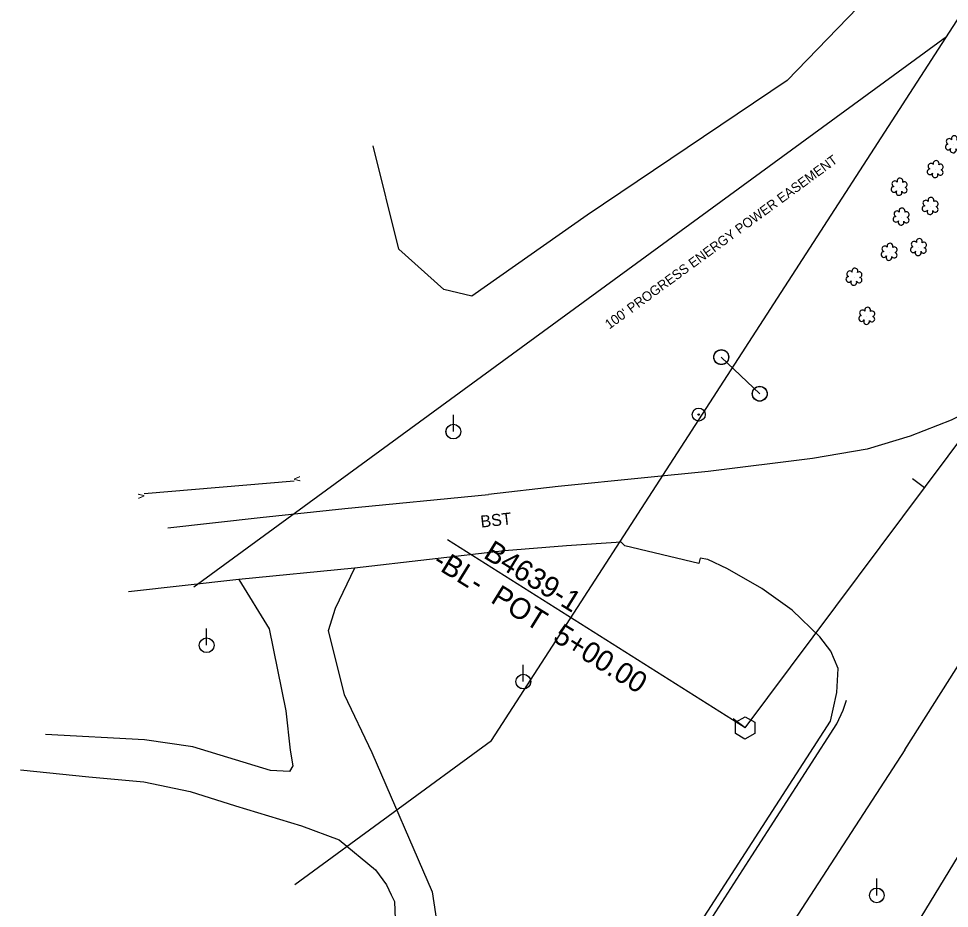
# Model space of a CAD drawing. Extents: x 1840200 to 1849051, y 348278 to 353012.
# Drawn here: x 1843953.5 to 1844264.2, y 349980.4 to 350277.2 of the extents above; entities that cross this region are included whole.
import ezdxf

# ---------------------------------------------------------------- set-up
doc = ezdxf.new("R2010")
doc.units = 0
for name, color, linetype in [('CTL GPS Vertical CELL', 7, 'Continuous'), ('Default', 7, 'Continuous'), ('Exist Horizontal Baseline Alignment', 7, 'Continuous'), ('Exist Horizontal Baseline Alignment Station Label', 7, 'Continuous'), ('Exist Horizontal Baseline Alignment Tick small', 7, 'Continuous'), ('Exist Right of Way Easement Line', 7, 'Continuous'), ('Exist Right of Way Easement Line Text', 7, 'Continuous'), ('Exist Right of Way Line', 7, 'Continuous'), ('Exist Roads EOP', 7, 'Continuous'), ('Exist Roads EOP Text', 7, 'Continuous'), ('Exist Roads EOT', 7, 'Continuous'), ('Exist Roads Soil', 7, 'Continuous'), ('Exist Structure Minor Culvert Topo', 7, 'Continuous'), ('Exist Utilities Other Located Object CELL', 7, 'Continuous'), ('Exist Utilities Other Pole CELL', 7, 'Continuous'), ('Exist Utilities Power H-Frame Pole CELL', 7, 'Continuous'), ('Exist Utilities Power Pole CELL', 7, 'Continuous'), ('Exist Vegetation Shrub CELL', 7, 'Continuous'), ('Exist Vegetation Woods Line', 7, 'Continuous')]:
    doc.layers.add(name, color=color, linetype=linetype)

# ---------------------------------------------------------------- blocks, each defined once
blk = doc.blocks.new('EXIST UTILITIES OTHER POLE')
at = {"layer": 'Exist Utilities Other Pole CELL'}
blk.add_circle((0, 0), 0.0493, dxfattribs=at)
blk = doc.blocks.new('EXIST UTILITIES OTHER LOCATED OBJECT')
at = {"layer": 'Exist Utilities Other Located Object CELL'}
for radius in [0.0436, 0.0048]:
    blk.add_circle((0, 0), radius, dxfattribs=at)
blk = doc.blocks.new('EXIST VEGETATION SHRUB')
at = {"layer": 'Exist Vegetation Shrub CELL'}
blk.add_line((0, 0), (0, 0), dxfattribs=at)
for centre, radius, start, end in [((-0.036, -0.0141), 0.0191, 95.10992, 327.95341), ((-0.0297, 0.0225), 0.0194, 35.89076, 245.42165), ((0.0046, 0.0408), 0.0198, 334.83907, 200.47174), ((0.0334, 0.0174), 0.0186, 284.45672, 126.08612), ((-0.0026, -0.0337), 0.0197, 151.27966, 21.38702), ((0.0327, -0.0186), 0.0187, 204.99133, 73.46012)]:
    blk.add_arc(centre, radius, start, end, dxfattribs=at)
blk = doc.blocks.new('EXIST UTILITIES POWER POLE')
at = {"layer": 'Exist Utilities Power Pole CELL'}
for q in [(0, 0.1125), (0, 0)]:
    blk.add_line((0, 0), q, dxfattribs=at)
blk.add_circle((0, 0), 0.049, dxfattribs=at)

msp = doc.modelspace()

# ---------------------------------------------------------------- linework, layer by layer
at = {"layer": 'CTL GPS Vertical CELL'}
msp.add_line((1844196.03, 350040.6), (1844196.03, 350040.6), dxfattribs=at)
msp.add_lwpolyline([(1844192.8, 350042.47), (1844196.05, 350044.28), (1844199.3, 350042.49), (1844199.25, 350038.77), (1844196, 350036.88), (1844192.8, 350038.69)], close=True, dxfattribs=at)
at = {"layer": 'Exist Horizontal Baseline Alignment'}
msp.add_line((1844196.06, 350040.59), (1844672.71, 350678.49), dxfattribs=at)
at = {"layer": 'Exist Horizontal Baseline Alignment Station Label'}
msp.add_line((1844196.06, 350040.59), (1844096.72, 350103.34), dxfattribs=at)
at = {"layer": 'Exist Horizontal Baseline Alignment Tick small'}
for p, q in [((1844255.92, 350120.7), (1844251.91, 350123.69)), ((1844196.06, 350040.59), (1844192.05, 350043.58))]:
    msp.add_line(p, q, dxfattribs=at)
at = {"layer": 'Exist Right of Way Easement Line'}
for p, q in [((1844012.08, 350087.68), (1844263.22, 350271.31)), ((1844045.7, 349988.37), (1844111.41, 350036.42))]:
    msp.add_line(p, q, dxfattribs=at)
at = {"layer": 'Exist Right of Way Line'}
msp.add_line((1844111.41, 350036.42), (1844314.94, 350351.32), dxfattribs=at)
at = {"layer": 'Exist Roads EOP'}
for points in [[(1844316.76, 350184.04), (1844310.83, 350175.6), (1844307.04, 350171.32), (1844285.83, 350155.26), (1844278.81, 350150.27), (1844264.85, 350143.3), (1844251.15, 350137.9), (1844236.78, 350133.54), (1844218.56, 350130.52), (1844183.75, 350126.16), (1844162.49, 350124), (1844133.66, 350121.08), (1844110.34, 350118.47)], [(1844249.35, 350033.32), (1844292.81, 350101.84), (1844337.61, 350171.08)], [(1844003.3, 350107.3), (1844034.19, 350110.76), (1844062.41, 350113.8), (1844110.34, 350118.47)], [(1844136.44, 350101.34), (1844115.71, 350099.69), (1844065.63, 350093.91), (1844027.04, 350090.05), (1843990.2, 350086.03)], [(1844226.7, 350052.39), (1844227.09, 350060.42), (1844224.62, 350066.2), (1844220.98, 350071.02), (1844211.77, 350079.88), (1844201.62, 350087.14), (1844190.18, 350093.61), (1844183.63, 350096.8), (1844181.05, 350097.17), (1844180.64, 350095.45), (1844155.88, 350101.29), (1844154.66, 350102.56), (1844136.44, 350101.34)], [(1843953.54, 349614.62), (1843979.84, 349656.88), (1843992.92, 349677.81), (1843994.32, 349682.6), (1844055.09, 349778.44), (1844139.39, 349910.12), (1844177.9, 349970.62), (1844224.49, 350042.87), (1844225.38, 350046.89), (1844226.7, 350052.39)], [(1844249.35, 350033.32), (1844201.2, 349959.08), (1844152.57, 349882.73), (1844105.59, 349809.27), (1844059.62, 349737.01), (1844009.61, 349658.33), (1843974.36, 349602.86)]]:
    msp.add_lwpolyline(points, dxfattribs=at)
at = {"layer": 'Exist Roads EOT'}
msp.add_lwpolyline([(1843995.34, 349679.65), (1844028.05, 349731.26), (1844074.33, 349803.82), (1844117.6, 349871.45), (1844156.2, 349932.5), (1844198.3, 349997.92), (1844226.68, 350041.93), (1844228.78, 350046.47), (1844229.93, 350049.83)], dxfattribs=at)
at = {"layer": 'Exist Roads Soil'}
for points in [[(1844065.63, 350093.91), (1844059.24, 350080.41), (1844056.84, 350073.01), (1844062.16, 350051.78), (1844071.47, 350032.41), (1844091.61, 349985.9), (1844094.41, 349967.53), (1844097.71, 349953.77), (1844104.12, 349929.43), (1844119.1, 349920.54), (1844142.85, 349915.25)], [(1844027.04, 350090.05), (1844037.21, 350073.64), (1844042.79, 350046.32), (1844044.19, 350033.2), (1844045.04, 350027.99), (1844043.92, 350026.1), (1844037.67, 350026.42), (1844011.69, 350034.3), (1843995.56, 350036.58), (1843962.46, 350038.34)], [(1843954.12, 350026.55), (1843976.98, 350024.23), (1843995.37, 350022.57), (1844010.8, 350019.39), (1844025.93, 350014.64), (1844047.97, 350007.91), (1844060.58, 350003.3), (1844072.64, 349993.27), (1844076.38, 349988.25), (1844077.92, 349984.93), (1844078.99, 349982.66), (1844079.23, 349976.79), (1844073.31, 349959.6), (1844060.9, 349938.33), (1844030.63, 349897.06), (1844025.36, 349888.87)]]:
    msp.add_lwpolyline(points, dxfattribs=at)
at = {"layer": 'Exist Structure Minor Culvert Topo'}
msp.add_lwpolyline([(1844045.54, 350122.94), (1843995.42, 350118.65)], dxfattribs=at)
at = {"layer": 'Exist Utilities Power H-Frame Pole CELL'}
msp.add_line((1844200.92, 350152.07), (1844188.08, 350164.28), dxfattribs=at)
for centre in [(1844188.08, 350164.28), (1844200.92, 350152.07)]:
    msp.add_circle(centre, 2.5, dxfattribs=at)
at = {"layer": 'Exist Vegetation Woods Line'}
for points in [[(1844616.63, 350690.01), (1844572.44, 350616.14), (1844513.95, 350532.41), (1844449.49, 350471.85), (1844374.19, 350416.85), (1844306.59, 350358.49), (1844270.69, 350319.29), (1844210.03, 350256.61), (1844143.34, 350211.7), (1844104.77, 350184.58), (1844095.43, 350186.87), (1844080.51, 350200.35), (1844071.84, 350234.77)], [(1844019.02, 349623.22), (1844073.69, 349707.12), (1844150.32, 349822.65), (1844217.8, 349918.12), (1844245.45, 349962.07), (1844278.2, 350015.83), (1844293.1, 350029.39)]]:
    msp.add_lwpolyline(points, dxfattribs=at)

# ---------------------------------------------------------------- block references
at = {"layer": 'Default', "xscale": 50, "yscale": 50}
for name, p in [('EXIST VEGETATION SHRUB', (1844265.64, 350235.1)), ('EXIST VEGETATION SHRUB', (1844259.56, 350226.84)), ('EXIST VEGETATION SHRUB', (1844247.52, 350220.97)), ('EXIST VEGETATION SHRUB', (1844257.87, 350214.54)), ('EXIST VEGETATION SHRUB', (1844248.2, 350210.98)), ('EXIST VEGETATION SHRUB', (1844253.96, 350200.82)), ('EXIST VEGETATION SHRUB', (1844244.18, 350199.24)), ('EXIST VEGETATION SHRUB', (1844232.46, 350190.94)), ('EXIST VEGETATION SHRUB', (1844236.72, 350177.89)), ('EXIST UTILITIES OTHER POLE', (1844188.08, 350164.28)), ('EXIST UTILITIES OTHER POLE', (1844200.92, 350152.07)), ('EXIST UTILITIES OTHER LOCATED OBJECT', (1844180.55, 350145.13)), ('EXIST UTILITIES OTHER POLE', (1844098.66, 350139.44)), ('EXIST UTILITIES OTHER POLE', (1844016.31, 350068.17)), ('EXIST UTILITIES OTHER POLE', (1844122.01, 350056.05)), ('EXIST UTILITIES OTHER POLE', (1844240, 349984.7))]:
    msp.add_blockref(name, p, dxfattribs=at)
at = {"layer": 'Exist Utilities Power Pole CELL', "xscale": 50, "yscale": 50}
for p in [(1844098.66, 350139.44), (1844016.31, 350068.17), (1844122.01, 350056.05), (1844240, 349984.7)]:
    msp.add_blockref('EXIST UTILITIES POWER POLE', p, dxfattribs=at)

# ---------------------------------------------------------------- texts
at = {"layer": 'Exist Horizontal Baseline Alignment Station Label'}
for s, p in [('     B4639-1', (1844097.3, 350104.42)), ('-BL-  POT  5+00.00', (1844091.3, 350094.76))]:
    msp.add_text(s, height=7, rotation=328.1568, dxfattribs=at).set_placement(p)
at = {"layer": 'Exist Right of Way Easement Line Text'}
msp.add_text("100' PROGRESS ENERGY POWER EASEMENT", height=3.2, rotation=36.175, dxfattribs=at).set_placement((1844150.71, 350173.46))
at = {"layer": 'Exist Roads EOP Text'}
msp.add_text('BST', height=4, rotation=6.3796, dxfattribs=at).set_placement((1844107.92, 350107.39))
at = {"layer": 'Exist Structure Minor Culvert Topo'}
for rotation, p in [(274.6519, (1844045.42, 350124.44)), (95.1336, (1843995.55, 350117.16))]:
    msp.add_text('v', height=2.65, rotation=rotation, dxfattribs=at).set_placement(p)

doc.saveas('drawing.dxf')
